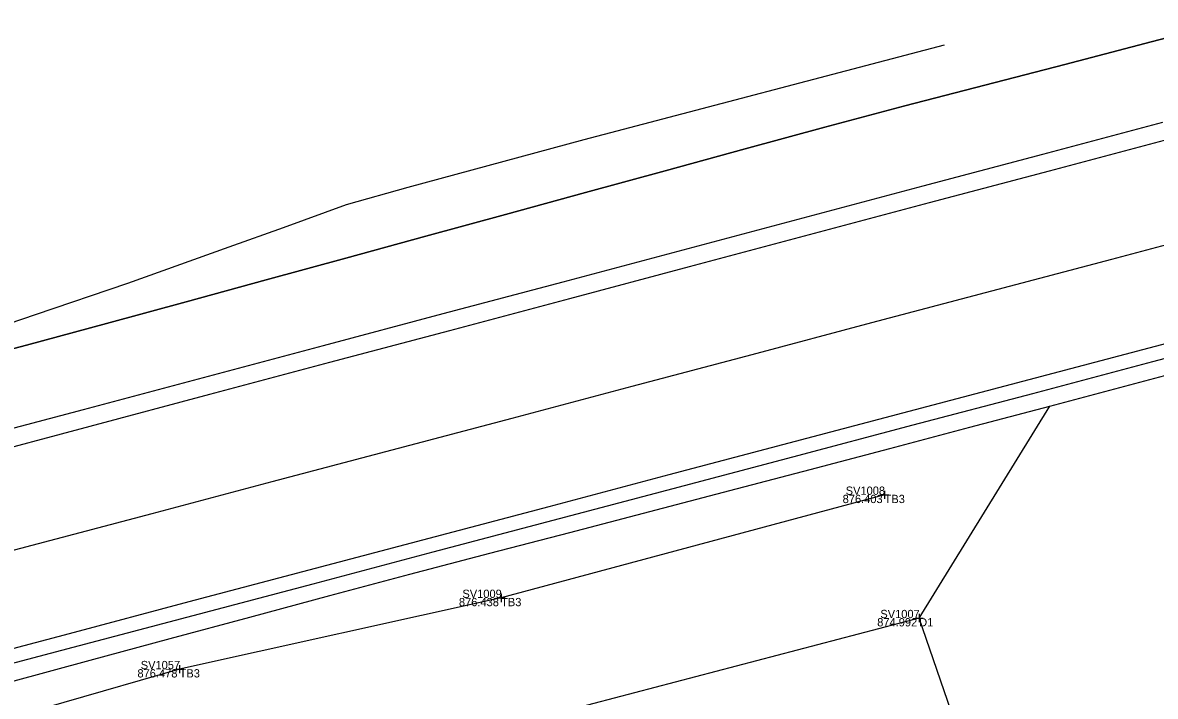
# Model space of a CAD drawing. Extents: x 2125299 to 2129212, y 713100 to 714300.
# Drawn here: x 2128517.6 to 2128654.5, y 714115.5 to 714196.9 of the extents above; entities that cross this region are included whole.
import ezdxf

# ---------------------------------------------------------------- set-up
doc = ezdxf.new("R2010")
doc.units = 0
for name, color, linetype in [('_CIVIL_CONSTRUCTION', 7, 'Continuous'), ('DR_X_Ditch', 7, 'Continuous'), ('DT_X_Terrain_Boundary', 7, 'Continuous'), ('PV_X_EOP', 7, 'Continuous'), ('PV_X_Shoulder_Rumble_Strip', 7, 'Continuous'), ('RW_P_Esmt_TMP', 7, 'Continuous'), ('RW_X_Esmt_CH', 7, 'Continuous'), ('RW_X_Fee_WL', 7, 'Continuous'), ('SC_Scratch1', 7, 'Continuous'), ('SC_Scratch2', 7, 'Continuous'), ('SV_X_Mon_Cells_Found', 7, 'Continuous'), ('SV_X_Top_of_Bank', 7, 'Continuous')]:
    doc.layers.add(name, color=color, linetype=linetype)

msp = doc.modelspace()

# ---------------------------------------------------------------- linework, layer by layer
at = {"layer": '_CIVIL_CONSTRUCTION'}
msp.add_lwpolyline([(2128402.73, 714103.07), (2128417.23, 714106.91), (2128431.73, 714110.76), (2128446.23, 714114.6), (2128460.73, 714118.44), (2128475.23, 714122.28), (2128489.73, 714126.12), (2128504.23, 714129.96), (2128518.73, 714133.8), (2128533.23, 714137.64), (2128547.73, 714141.49), (2128562.23, 714145.33), (2128576.73, 714149.17), (2128591.23, 714153.01), (2128605.73, 714156.85), (2128620.23, 714160.69), (2128634.73, 714164.53), (2128649.23, 714168.37), (2128663.73, 714172.21)], dxfattribs=at)
at = {"layer": 'DR_X_Ditch'}
msp.add_lwpolyline([(2128625.93, 714124.99), (2128579.25, 714112.76), (2128539.45, 714102.67), (2128534.31, 714100.87)], dxfattribs=at)
at = {"layer": 'DT_X_Terrain_Boundary'}
for points in [[(2128662.9, 714196.94), (2128653.22, 714194.42), (2128643.55, 714191.9), (2128633.87, 714189.39), (2128624.19, 714186.87), (2128614.52, 714184.32), (2128604.88, 714181.68), (2128595.23, 714179.04), (2128585.58, 714176.41), (2128575.94, 714173.77), (2128566.29, 714171.13), (2128556.64, 714168.5), (2128547, 714165.86), (2128537.35, 714163.22), (2128527.71, 714160.59), (2128518.05, 714157.98), (2128508.38, 714155.45), (2128442.63, 714160.2), (2128404.43, 714186.27)], [(2128661.46, 714076.82), (2128651.78, 714074.32), (2128636.61, 714089.66), (2128635.11, 714093.62), (2128632.64, 714103.31), (2128631.32, 714108.2), (2128630.23, 714112.45), (2128625.93, 714124.99), (2128641.74, 714150.62), (2128651.4, 714153.18), (2128661.07, 714155.74)]]:
    msp.add_lwpolyline(points, dxfattribs=at)
at = {"layer": 'PV_X_EOP'}
for points in [[(2128508.38, 714155.45), (2128518.05, 714157.98), (2128527.71, 714160.59), (2128537.35, 714163.22), (2128547, 714165.86), (2128556.64, 714168.5), (2128566.29, 714171.13), (2128575.94, 714173.77), (2128585.58, 714176.41), (2128595.23, 714179.04), (2128604.88, 714181.68), (2128614.52, 714184.32), (2128624.19, 714186.87), (2128633.87, 714189.39), (2128643.55, 714191.9), (2128653.22, 714194.42), (2128662.9, 714196.94)], [(2128516.08, 714117.3), (2128525.73, 714119.91), (2128535.39, 714122.51), (2128545.04, 714125.12), (2128554.7, 714127.72), (2128564.36, 714130.3), (2128574.04, 714132.83), (2128583.71, 714135.35), (2128593.39, 714137.88), (2128603.06, 714140.4), (2128612.74, 714142.94), (2128622.4, 714145.5), (2128632.07, 714148.06), (2128641.74, 714150.62), (2128651.4, 714153.18), (2128661.07, 714155.74)]]:
    msp.add_lwpolyline(points, dxfattribs=at)
at = {"layer": 'PV_X_Shoulder_Rumble_Strip'}
for points in [[(2128408.92, 714119.5), (2128423.43, 714123.32), (2128437.93, 714127.15), (2128452.44, 714130.97), (2128466.94, 714134.8), (2128481.44, 714138.64), (2128495.93, 714142.5), (2128510.43, 714146.36), (2128524.93, 714150.21), (2128539.42, 714154.07), (2128553.92, 714157.93), (2128568.41, 714161.78), (2128582.91, 714165.64), (2128597.41, 714169.49), (2128611.9, 714173.35), (2128626.4, 714177.21), (2128640.89, 714181.06), (2128655.39, 714184.92)], [(2128407.66, 714090.8), (2128422.17, 714094.63), (2128436.67, 714098.47), (2128451.17, 714102.3), (2128465.67, 714106.14), (2128480.17, 714109.97), (2128494.67, 714113.81), (2128509.17, 714117.64), (2128523.68, 714121.48), (2128538.18, 714125.32), (2128552.68, 714129.15), (2128567.18, 714132.99), (2128581.68, 714136.82), (2128596.18, 714140.66), (2128610.68, 714144.49), (2128625.19, 714148.33), (2128639.69, 714152.15), (2128654.19, 714155.98), (2128668.69, 714159.81)]]:
    msp.add_lwpolyline(points, dxfattribs=at)
at = {"layer": 'SC_Scratch1'}
msp.add_lwpolyline([(2128628.95, 714194.22), (2128585.4, 714182.79), (2128564.12, 714177.04), (2128556.66, 714174.91), (2128549.07, 714172.15), (2128542.5, 714169.81), (2128530.23, 714165.43), (2128519.08, 714161.63), (2128507.97, 714157.87), (2128491.85, 714153.02), (2128450.41, 714141.74), (2128284.96, 714097.53), (2128098.63, 714048.44)], dxfattribs=at)
at = {"layer": 'SC_Scratch2'}
for points in [[(2128409.71, 714117.48), (2128424.21, 714121.3), (2128438.72, 714125.13), (2128453.22, 714128.95), (2128467.73, 714132.78), (2128482.23, 714136.62), (2128496.72, 714140.48), (2128511.22, 714144.33), (2128525.71, 714148.19), (2128540.21, 714152.05), (2128554.7, 714155.9), (2128569.2, 714159.76), (2128583.7, 714163.62), (2128598.19, 714167.47), (2128612.69, 714171.33), (2128627.18, 714175.19), (2128641.68, 714179.04), (2128656.18, 714182.9)], [(2128407.2, 714092.47), (2128421.7, 714096.3), (2128436.2, 714100.14), (2128450.7, 714103.97), (2128465.2, 714107.81), (2128479.7, 714111.64), (2128494.21, 714115.48), (2128508.71, 714119.31), (2128523.21, 714123.15), (2128537.71, 714126.98), (2128552.21, 714130.82), (2128566.71, 714134.66), (2128581.21, 714138.49), (2128595.72, 714142.33), (2128610.22, 714146.16), (2128624.72, 714150), (2128639.22, 714153.82), (2128653.73, 714157.65), (2128668.23, 714161.48)]]:
    msp.add_lwpolyline(points, dxfattribs=at)
at = {"layer": 'SV_X_Mon_Cells_Found'}
for p, q in [((2128621.75, 714140.39), (2128621.75, 714139.39)), ((2128621.25, 714139.89), (2128622.25, 714139.89)), ((2128621.75, 714139.89), (2128621.75, 714139.89)), ((2128575.4, 714127.93), (2128575.4, 714126.93)), ((2128574.9, 714127.43), (2128575.9, 714127.43)), ((2128575.4, 714127.43), (2128575.4, 714127.43)), ((2128625.43, 714124.99), (2128626.43, 714124.99)), ((2128625.93, 714125.49), (2128625.93, 714124.49)), ((2128625.93, 714124.99), (2128625.93, 714124.99)), ((2128536.04, 714118.82), (2128537.04, 714118.82)), ((2128536.54, 714119.32), (2128536.54, 714118.32)), ((2128536.54, 714118.82), (2128536.54, 714118.82))]:
    msp.add_line(p, q, dxfattribs=at)
at = {"layer": 'SV_X_Top_of_Bank'}
msp.add_lwpolyline([(2128621.75, 714139.89), (2128575.4, 714127.43), (2128536.54, 714118.82), (2128494.56, 714106.73), (2128494.59, 714106.74), (2128431.42, 714092.25), (2128387.26, 714080.92), (2128325.7, 714062.91), (2128270.25, 714048.29), (2128232.44, 714039), (2128192.57, 714028.85), (2128120.54, 714010.42)], dxfattribs=at)

# ---------------------------------------------------------------- texts
at = {"layer": 'RW_P_Esmt_TMP'}
for s, p in [('TB3', (2128621.75, 714138.89)), ('TB3', (2128575.4, 714126.43)), ('D1', (2128625.93, 714123.99)), ('TB3', (2128536.54, 714117.82))]:
    msp.add_text(s, height=1, dxfattribs=at).set_placement(p)
at = {"layer": 'RW_X_Esmt_CH'}
for s, p in [('SV1008', (2128617.05, 714139.89)), ('SV1009', (2128570.72, 714127.43)), ('SV1007', (2128621.24, 714124.99)), ('SV1057', (2128531.84, 714118.82))]:
    msp.add_text(s, height=1, dxfattribs=at).set_placement(p)
at = {"layer": 'RW_X_Fee_WL'}
for s, p in [('876.403', (2128616.68, 714138.89)), ('876.438', (2128570.3, 714126.43)), ('874.992', (2128620.86, 714123.99)), ('876.478', (2128531.44, 714117.82))]:
    msp.add_text(s, height=1, dxfattribs=at).set_placement(p)

doc.saveas('drawing.dxf')
